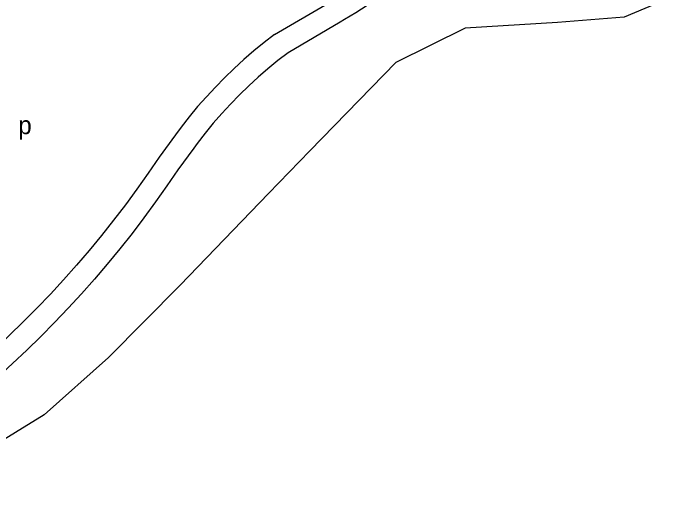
# Model space of a CAD drawing. Extents: x 159700 to 161346, y 381730 to 382922.
# Drawn here: x 161168.6 to 161316.2, y 382029.5 to 382139.7 of the extents above; entities that cross this region are included whole.
import ezdxf

# ---------------------------------------------------------------- set-up
doc = ezdxf.new("R2010")
doc.units = 0
doc.layers.add('BLT_Basislijn', color=7, linetype='Continuous')
doc.layers.add('BLT_Centroide', color=7, linetype='Continuous')

msp = doc.modelspace()

# ---------------------------------------------------------------- linework, layer by layer
at = {"layer": 'BLT_Basislijn'}
for p, q in [((161226.29, 382134.98), (161238.25, 382142.02)), ((161240.75, 382137.69), (161229.29, 382130.98)), ((161204.39, 382112.88), (161200.8, 382107.95)), ((161208.43, 382109.93), (161204.96, 382105.18))]:
    msp.add_line(p, q, dxfattribs=at)
for points in [[(161298.63, 382177.96), (161297.16, 382171.27), (161308.89, 382165.4), (161313.65, 382162.61), (161316.19, 382152.06), (161315.26, 382146.22), (161310.37, 382141.69), (161303.47, 382138.82), (161288.77, 382137.61), (161268.37, 382136.43), (161253.09, 382128.79)], [(161270.45, 382163.02), (161268.57, 382160.77), (161266.63, 382158.57), (161264.63, 382156.43), (161262.58, 382154.34), (161260.46, 382152.31), (161258.3, 382150.34), (161256.08, 382148.42), (161253.81, 382146.57), (161251.49, 382144.78), (161249.12, 382143.05), (161246.71, 382141.39), (161244.25, 382139.8), (161241.74, 382138.28), (161240.75, 382137.69)], [(161226.29, 382134.98), (161223.98, 382133.2), (161221.73, 382131.36), (161219.52, 382129.46), (161217.37, 382127.49), (161215.27, 382125.47), (161213.22, 382123.4), (161211.24, 382121.26), (161209.31, 382119.08), (161207.45, 382116.84), (161205.65, 382114.55), (161204.39, 382112.88)], [(161229.29, 382130.98), (161227.04, 382129.24), (161224.83, 382127.44), (161222.68, 382125.58), (161220.59, 382123.66), (161218.54, 382121.68), (161216.56, 382119.65), (161214.63, 382117.55), (161212.76, 382115.41), (161210.95, 382113.22), (161209.21, 382110.97), (161208.43, 382109.93)], [(161253.09, 382128.79), (161234.07, 382109.37), (161224.99, 382099.9), (161205.45, 382079.68)], [(161200.8, 382107.95), (161198.38, 382104.4), (161195.9, 382100.89), (161193.36, 382097.43), (161190.75, 382094.02), (161188.08, 382090.66), (161185.35, 382087.35), (161182.56, 382084.09), (161179.71, 382080.88), (161176.79, 382077.73), (161173.82, 382074.63), (161170.79, 382071.59), (161167.71, 382068.6), (161164.57, 382065.67), (161161.37, 382062.8), (161158.13, 382059.99), (161154.83, 382057.24), (161151.48, 382054.56), (161148.08, 382051.94), (161144.63, 382049.38), (161142.67, 382047.96)], [(161204.96, 382105.18), (161202.52, 382101.59), (161200.02, 382098.05), (161197.45, 382094.55), (161194.81, 382091.1), (161192.12, 382087.7), (161189.36, 382084.35), (161186.54, 382081.05), (161183.66, 382077.8), (161180.72, 382074.61), (161177.72, 382071.47), (161174.67, 382068.39), (161171.56, 382065.36), (161168.39, 382062.4), (161165.17, 382059.49), (161161.9, 382056.64), (161158.57, 382053.85), (161155.2, 382051.12), (161151.77, 382048.46), (161148.3, 382045.86), (161145.58, 382043.9)], [(161205.45, 382079.68), (161189.62, 382063.77), (161175.39, 382051.08)], [(161175.39, 382051.08), (161162.7, 382043.3), (161139.82, 382029.53)]]:
    msp.add_lwpolyline(points, dxfattribs=at)

# ---------------------------------------------------------------- texts
at = {"layer": 'BLT_Centroide'}
msp.add_text('p', height=4, dxfattribs=at).set_placement((161169.69, 382113.01))

doc.saveas('drawing.dxf')
